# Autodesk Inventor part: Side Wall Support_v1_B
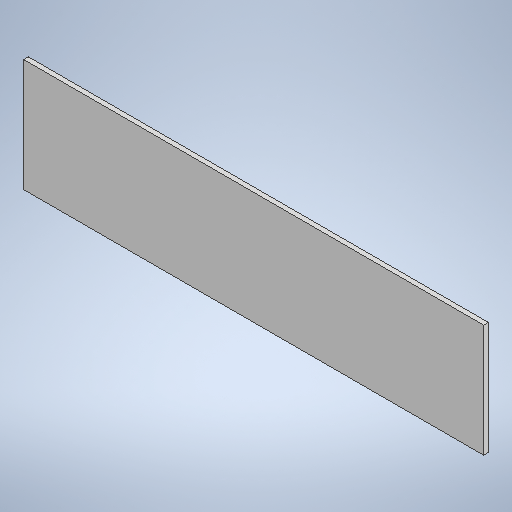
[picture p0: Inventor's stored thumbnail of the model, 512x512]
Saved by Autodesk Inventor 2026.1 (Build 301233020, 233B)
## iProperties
Created: 2026-10
Part Number: Side Wall Support_v1_B
Material: Generic
Document SubType Name: Modeling
Designer: hp
Density: 1 g/cm^3
Appearance: Default
Author: hp
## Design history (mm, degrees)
sketch "Sketch1"
  geometry: L1 (0, 0)-(540, 0); L2 (540, 120)-(0, 120); L3 (0, 120)-(0, 0); L4 (540, 120)-(540, 0); L5 (50, 120)-(50, 0)
  constraints: 10 end point, 2 point on line, 1 horizontal, 1 parallel, 1 perpendicular, 1 vertical
  dimensions: "d28" = 540 distance of L2.start L2.end; "d29" = 120 distance of L2.end L1.start; "d48" = 50 distance between parallel lines of L3 L5
extrude "Extrusion2" new body sketch "Sketch1" distance "d23" = 5; taper "d24" = 0 deg
body "Solid2"
